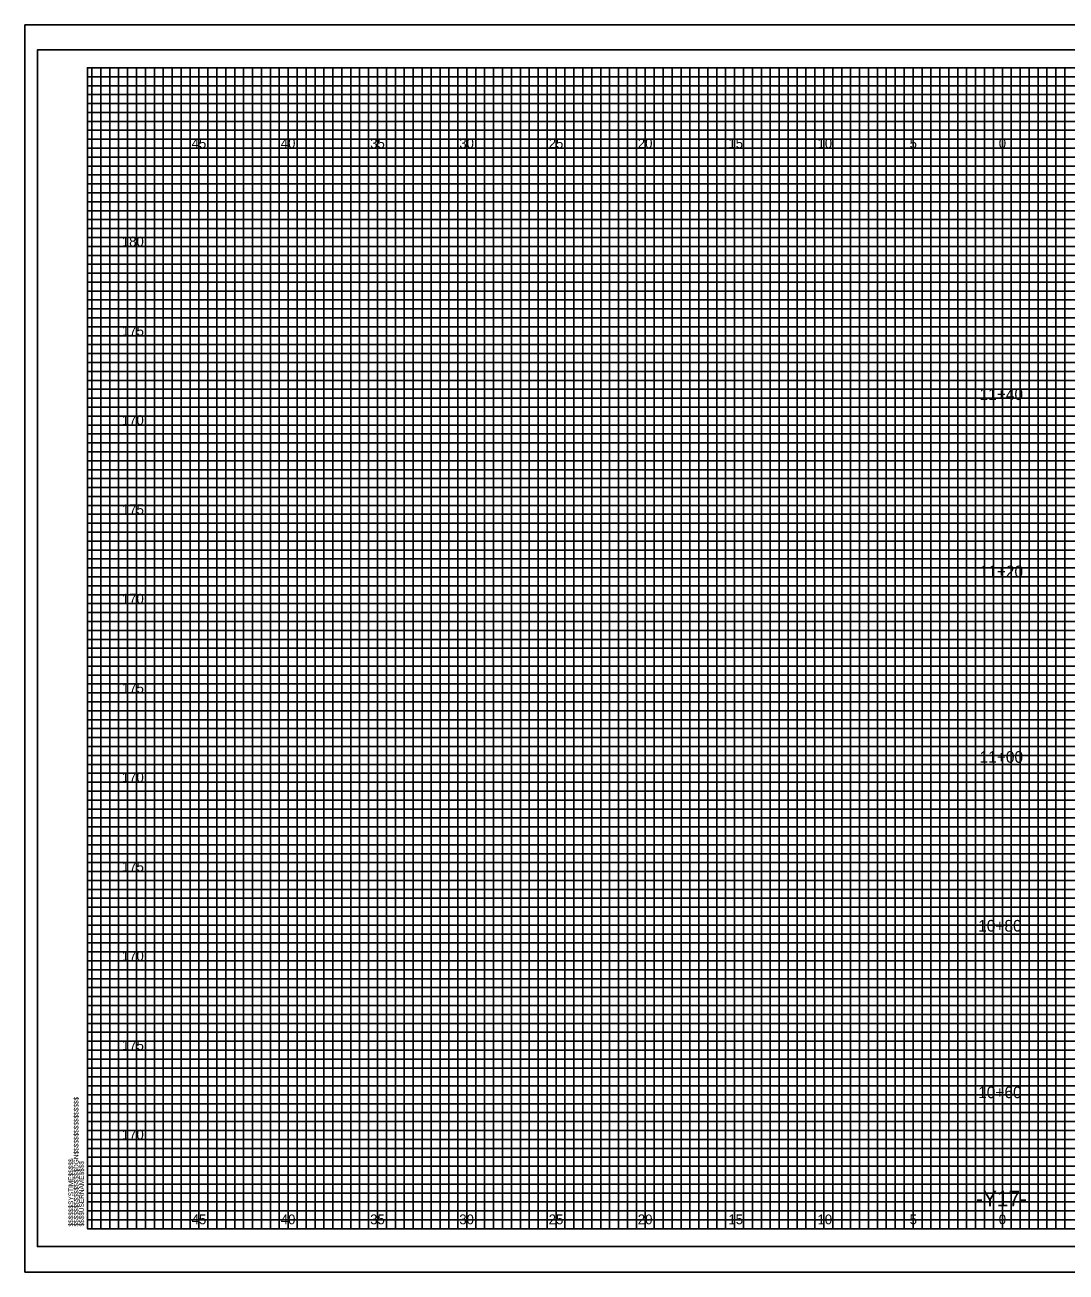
# Model space of a CAD drawing. Extents: x -4 to 103, y -2 to 209.
# Drawn here: x -3.5 to 54.8, y -2.4 to 67.4 of the extents above; entities that cross this region are included whole.
import ezdxf

# ---------------------------------------------------------------- set-up
doc = ezdxf.new("R2010")
doc.units = 0
for name, color, linetype in [('Prop XS Alignment Label', 7, 'Continuous'), ('Prop XS Elevation Labels', 7, 'Continuous'), ('Prop XS Offset Labels', 7, 'Continuous'), ('Prop XS Station Labels', 7, 'Continuous'), ('Sheet Cross Section CELL', 7, 'Continuous'), ('Sheet Cross Section Grid Major CELL', 7, 'Continuous'), ('Sheet Cross Section Grid Middle CELL', 7, 'Continuous'), ('Sheet Cutting Line CELL', 7, 'Continuous'), ('Sheet DOT Grid CELL', 7, 'Continuous'), ('Sheet Plot Border Inside CELL', 7, 'Continuous'), ('Sheet Plot Border Outside CELL', 7, 'Continuous')]:
    doc.layers.add(name, color=color, linetype=linetype)

msp = doc.modelspace()

# ---------------------------------------------------------------- linework, layer by layer
at = {"layer": 'Sheet Cross Section CELL'}
msp.add_lwpolyline([(102.5, 65), (0, 65), (0, 0), (102.5, 0)], close=True, dxfattribs=at)
at = {"layer": 'Sheet Cross Section Grid Major CELL'}
for points in [[(1.25, 0), (1.25, 65), (3.75, 65), (3.75, 0), (6.25, 0), (6.25, 65), (8.75, 65), (8.75, 0), (11.25, 0), (11.25, 65), (13.75, 65), (13.75, 0), (16.25, 0), (16.25, 65), (18.75, 65), (18.75, 0), (21.25, 0), (21.25, 65), (23.75, 65), (23.75, 0), (26.25, 0), (26.25, 65), (28.75, 65), (28.75, 0), (31.25, 0), (31.25, 65), (33.75, 65), (33.75, 0), (36.25, 0), (36.25, 65), (38.75, 65), (38.75, 0), (41.25, 0), (41.25, 65), (43.75, 65), (43.75, 0), (46.25, 0), (46.25, 65), (48.75, 65), (48.75, 0), (51.25, 0), (51.25, 65), (53.75, 65), (53.75, 0)], [(102.5, 60), (0, 60), (0, 62.5), (74.25, 62.5)], [(102.5, 55), (0, 55), (0, 57.5), (102.5, 57.5)], [(102.5, 50), (0, 50), (0, 52.5), (102.5, 52.5)], [(102.5, 45), (0, 45), (0, 47.5), (102.5, 47.5)], [(102.5, 40), (0, 40), (0, 42.5), (102.5, 42.5)], [(102.5, 35), (0, 35), (0, 37.5), (102.5, 37.5)], [(102.5, 30), (0, 30), (0, 32.5), (102.5, 32.5)], [(102.5, 25), (0, 25), (0, 27.5), (102.5, 27.5)], [(102.5, 20), (0, 20), (0, 22.5), (102.5, 22.5)], [(102.5, 15), (0, 15), (0, 17.5), (102.5, 17.5)], [(102.5, 10), (0, 10), (0, 12.5), (102.5, 12.5)], [(102.5, 5), (0, 5), (0, 7.5), (102.5, 7.5)], [(0, 2.5), (102.5, 2.5)]]:
    msp.add_lwpolyline(points, dxfattribs=at)
at = {"layer": 'Sheet Cross Section Grid Middle CELL'}
for points in [[(0.25, 0), (0.25, 65), (0.75, 65), (0.75, 0), (1.75, 0), (1.75, 65), (2.25, 65), (2.25, 0), (2.75, 0), (2.75, 65), (3.25, 65), (3.25, 0), (4.25, 0), (4.25, 65), (4.75, 65), (4.75, 0), (5.25, 0), (5.25, 65), (5.75, 65), (5.75, 0), (6.75, 0), (6.75, 65), (7.25, 65), (7.25, 0), (7.75, 0), (7.75, 65), (8.25, 65), (8.25, 0), (9.25, 0), (9.25, 65), (9.75, 65), (9.75, 0), (10.25, 0), (10.25, 65), (10.75, 65), (10.75, 0), (11.75, 0), (11.75, 65), (12.25, 65), (12.25, 0), (12.75, 0), (12.75, 65), (13.25, 65), (13.25, 0), (14.25, 0), (14.25, 65), (14.75, 65), (14.75, 0), (15.75, 0), (15.25, 0), (15.25, 65), (15.75, 65), (15.75, 0), (16.75, 0), (16.75, 65), (17.25, 65), (17.25, 0), (17.75, 0), (17.75, 65), (18.25, 65), (18.25, 0), (19.25, 0), (19.25, 65), (19.75, 65), (19.75, 0), (20.25, 0), (20.25, 65), (20.75, 65), (20.75, 0), (21.75, 0), (21.75, 65), (22.25, 65), (22.25, 0), (22.75, 0), (22.75, 65), (23.25, 65), (23.25, 0), (24.25, 0), (24.25, 65), (24.75, 65), (24.75, 0), (25.25, 0), (25.25, 65), (25.75, 65), (25.75, 0), (26.75, 0), (26.75, 65), (27.25, 65), (27.25, 0), (27.75, 0), (27.75, 65), (28.25, 65), (28.25, 0), (29.25, 0), (29.25, 65), (29.75, 65), (29.75, 0), (30.25, 0), (30.25, 65), (30.75, 65), (30.75, 0)], [(30.75, 0), (31.75, 0), (31.75, 65), (32.25, 65), (32.25, 0), (32.75, 0), (32.75, 65), (33.25, 65), (33.25, 0), (34.25, 0), (34.25, 65), (34.75, 65), (34.75, 0), (35.25, 0), (35.25, 65), (35.75, 65), (35.75, 0), (36.75, 0), (36.75, 65), (37.25, 65), (37.25, 0), (37.75, 0), (37.75, 65), (37.75, 0)], [(38.25, 65), (38.25, 0), (39.25, 0), (39.25, 65), (39.75, 65), (39.75, 0), (40.25, 0), (40.25, 65), (40.75, 65), (40.75, 0), (41.75, 0), (41.75, 65), (42.25, 65), (42.25, 0), (42.75, 0), (42.75, 65), (43.25, 65), (43.25, 0), (43.75, 0), (44.25, 0), (44.25, 65), (44.75, 65), (44.75, 0), (45.25, 0), (45.25, 65), (45.75, 65), (45.75, 0), (46.75, 0), (46.75, 65), (47.25, 65), (47.25, 0), (47.75, 0), (47.75, 65), (48.25, 65), (48.25, 0), (49.25, 0), (49.25, 65), (49.75, 65), (49.75, 0), (50.25, 0), (50.25, 65), (50.75, 65), (50.75, 0), (51.75, 0), (51.75, 65), (52.25, 65), (52.25, 0), (52.75, 0), (52.75, 65), (53.25, 65), (53.25, 0), (54.25, 0), (54.25, 65), (54.75, 65), (54.75, 0), (55.25, 0)], [(0, 62), (0, 63), (74.25, 63), (74.25, 63.5), (0, 63.5), (0, 64), (74.25, 64), (74.25, 64.5), (0, 64.5)], [(102.5, 62), (0, 62)], [(102.5, 61), (0, 61), (0, 61.5), (102.5, 61.5)], [(102.5, 59.5), (0, 59.5), (0, 60.5), (102.5, 60.5)], [(102.5, 58.5), (0, 58.5), (0, 59), (102.5, 59)], [(102.5, 57), (0, 57), (0, 58), (102.5, 58)], [(102.5, 56), (0, 56), (0, 56.5), (102.5, 56.5)], [(102.5, 54.5), (0, 54.5), (0, 55.5), (102.5, 55.5)], [(102.5, 53.5), (0, 53.5), (0, 54), (102.5, 54)], [(0, 53), (102.5, 53)], [(102.5, 52), (0, 52)], [(102.5, 51), (0, 51), (0, 51.5), (102.5, 51.5)], [(102.5, 49.5), (0, 49.5), (0, 50.5), (102.5, 50.5)], [(102.5, 48.5), (0, 48.5), (0, 49), (102.5, 49)], [(102.5, 47), (0, 47), (0, 48), (102.5, 48)], [(102.5, 46), (0, 46), (0, 46.5), (102.5, 46.5)], [(102.5, 44.5), (0, 44.5), (0, 45.5), (102.5, 45.5)], [(102.5, 43.5), (0, 43.5), (0, 44), (102.5, 44)], [(102.5, 42), (0, 42), (0, 43), (102.5, 43)], [(102.5, 41), (0, 41), (0, 41.5), (102.5, 41.5)], [(102.5, 39.5), (0, 39.5), (0, 40.5), (102.5, 40.5)], [(102.5, 38.5), (0, 38.5), (0, 39), (102.5, 39)], [(102.5, 37), (0, 37), (0, 38), (102.5, 38)], [(102.5, 36), (0, 36), (0, 36.5), (102.5, 36.5)], [(102.5, 34.5), (0, 34.5), (0, 35.5), (102.5, 35.5)], [(102.5, 33.5), (0, 33.5), (0, 34), (102.5, 34)], [(102.5, 32), (0, 32), (0, 33), (102.5, 33)], [(102.5, 31), (0, 31), (0, 31.5)], [(0, 31.5), (102.5, 31.5)], [(102.5, 29.5), (0, 29.5), (0, 30.5), (102.5, 30.5)], [(102.5, 28.5), (0, 28.5), (0, 29), (102.5, 29)], [(102.5, 27), (0, 27), (0, 28), (102.5, 28)], [(102.5, 26), (0, 26), (0, 26.5), (102.5, 26.5)], [(102.5, 24.5), (0, 24.5), (0, 25.5), (102.5, 25.5)], [(102.5, 23.5), (0, 23.5), (0, 24), (102.5, 24)], [(102.5, 22), (0, 22), (0, 23), (102.5, 23)], [(102.5, 21), (0, 21), (0, 21.5), (102.5, 21.5)], [(102.5, 19.5), (0, 19.5), (0, 20.5), (102.5, 20.5)], [(102.5, 18.5), (0, 18.5), (0, 19), (102.5, 19)], [(102.5, 17), (0, 17), (0, 18), (102.5, 18)], [(102.5, 16), (0, 16), (0, 16.5), (102.5, 16.5)], [(102.5, 14.5), (0, 14.5), (0, 15.5), (102.5, 15.5)], [(102.5, 13.5), (0, 13.5), (0, 14), (102.5, 14)], [(102.5, 12), (0, 12), (0, 13), (102.5, 13)], [(102.5, 11), (0, 11), (0, 11.5), (102.5, 11.5)], [(102.5, 9.5), (0, 9.5), (0, 10.5), (102.5, 10.5)], [(102.5, 8.5), (0, 8.5), (0, 9), (102.5, 9)], [(102.5, 7), (0, 7), (0, 8), (102.5, 8)], [(102.5, 6), (0, 6), (0, 6.5), (102.5, 6.5)], [(102.5, 4.5), (0, 4.5), (0, 5.5), (102.5, 5.5)], [(102.5, 3.5), (0, 3.5), (0, 4), (102.5, 4)], [(102.5, 2), (0, 2), (0, 3), (102.5, 3)], [(102.5, 1), (0, 1), (0, 1.5), (102.5, 1.5)], [(0, 0.5), (102.5, 0.5)]]:
    msp.add_lwpolyline(points, dxfattribs=at)
at = {"layer": 'Sheet Cutting Line CELL'}
for p, q in [((-3.5, 67.4), (103.4, 67.4)), ((-3.5, 67.4), (-3.5, -2.425)), ((-3.5, -2.425), (103.4, -2.425))]:
    msp.add_line(p, q, dxfattribs=at)
at = {"layer": 'Sheet DOT Grid CELL'}
for p, q in [((1.25, 0), (1.25, 65)), ((3.75, 0), (3.75, 65)), ((6.25, 0), (6.25, 65)), ((8.75, 0), (8.75, 65)), ((11.25, 0), (11.25, 65)), ((13.75, 0), (13.75, 65)), ((16.25, 0), (16.25, 65)), ((18.75, 0), (18.75, 65)), ((21.25, 0), (21.25, 65)), ((23.75, 0), (23.75, 65)), ((26.25, 0), (26.25, 65)), ((28.75, 0), (28.75, 65)), ((31.25, 0), (31.25, 65)), ((33.75, 0), (33.75, 65)), ((36.25, 0), (36.25, 65)), ((38.75, 0), (38.75, 65)), ((41.25, 0), (41.25, 65)), ((43.75, 0), (43.75, 65)), ((46.25, 0), (46.25, 65)), ((48.75, 0), (48.75, 65)), ((51.25, 0), (51.25, 65)), ((53.75, 0), (53.75, 65)), ((0, 62.5), (74.25, 62.5)), ((0, 60), (102.5, 60)), ((0, 57.5), (102.5, 57.5)), ((0, 55), (102.5, 55)), ((0, 52.5), (102.5, 52.5)), ((0, 50), (102.5, 50)), ((0, 47.5), (102.5, 47.5)), ((0, 45), (102.5, 45)), ((0, 42.5), (102.5, 42.5)), ((0, 40), (102.5, 40)), ((0, 37.5), (102.5, 37.5)), ((0, 35), (102.5, 35)), ((0, 32.5), (102.5, 32.5)), ((0, 30), (102.5, 30)), ((0, 27.5), (102.5, 27.5)), ((0, 25), (102.5, 25)), ((0, 22.5), (102.5, 22.5)), ((0, 20), (102.5, 20)), ((0, 17.5), (102.5, 17.5)), ((0, 15), (102.5, 15)), ((0, 12.5), (102.5, 12.5)), ((0, 10), (102.5, 10)), ((0, 7.5), (102.5, 7.5)), ((0, 5), (102.5, 5)), ((0, 2.5), (102.5, 2.5))]:
    msp.add_line(p, q, dxfattribs=at)
at = {"layer": 'Sheet Plot Border Inside CELL'}
msp.add_lwpolyline([(103, 66), (-2.8, 66), (-2.8, -1), (103, -1)], close=True, dxfattribs=at)
at = {"layer": 'Sheet Plot Border Outside CELL'}
msp.add_lwpolyline([(103.4, 67.4), (-3.5, 67.4), (-3.5, -2.425), (103.4, -2.425)], close=True, dxfattribs=at)

# ---------------------------------------------------------------- texts
at = {"layer": 'Prop XS Alignment Label'}
msp.add_text('-Y17-', height=0.875, dxfattribs=at).set_placement((49.77311, 1.25))
at = {"layer": 'Prop XS Elevation Labels'}
for s, p in [('180', (1.92958, 55)), ('175', (1.93825, 50)), ('170', (1.92958, 45)), ('175', (1.93825, 40)), ('170', (1.92958, 35)), ('175', (1.93825, 30)), ('170', (1.92958, 25)), ('175', (1.93825, 20)), ('170', (1.92958, 15)), ('175', (1.93825, 10)), ('170', (1.92958, 5))]:
    msp.add_text(s, height=0.55, dxfattribs=at).set_placement(p)
at = {"layer": 'Prop XS Offset Labels'}
for s, p in [('45', (5.83992, 60.5)), ('40', (10.83125, 60.5)), ('35', (15.83992, 60.5)), ('30', (20.83125, 60.5)), ('25', (25.83992, 60.5)), ('20', (30.83125, 60.5)), ('15', (35.90575, 60.5)), ('10', (40.89708, 60.5)), ('5', (46.05742, 60.5)), ('0', (51.04875, 60.5)), ('0', (51.04875, 60.5)), ('45', (5.83992, 0.25)), ('40', (10.83125, 0.25)), ('35', (15.83992, 0.25)), ('30', (20.83125, 0.25)), ('25', (25.83992, 0.25)), ('20', (30.83125, 0.25)), ('15', (35.90575, 0.25)), ('10', (40.89708, 0.25)), ('5', (46.05742, 0.25)), ('0', (51.04875, 0.25)), ('0', (51.04875, 0.25))]:
    msp.add_text(s, height=0.55, dxfattribs=at).set_placement(p)
at = {"layer": 'Prop XS Station Labels'}
for s, p in [('11+40', (49.97117, 46.3995)), ('11+20', (49.97117, 36.4764)), ('11+00', (49.97117, 26.0914)), ('10+80', (49.89337, 16.6388)), ('10+60', (49.89337, 7.3133))]:
    msp.add_text(s, height=0.65, dxfattribs=at).set_placement(p)
at = {"layer": 'Sheet Cross Section CELL'}
for s, p in [('$$$$$$$$$$$$$$$$DGN$$$$$$$$$$$$$$$$', (-0.5, 0.125)), ('$$$$$$SYSTIME$$$$$', (-0.7973, 0.1247)), ('$$$$USERNAME$$$$', (-0.2, 0.125))]:
    msp.add_text(s, height=0.2625, rotation=90, dxfattribs=at).set_placement(p)
at = {"layer": 'Sheet Cross Section Grid Major CELL'}
msp.add_text('040397', height=0.0025, rotation=90, dxfattribs=at).set_placement((-0.0007, 64.9864))

doc.saveas('drawing.dxf')
